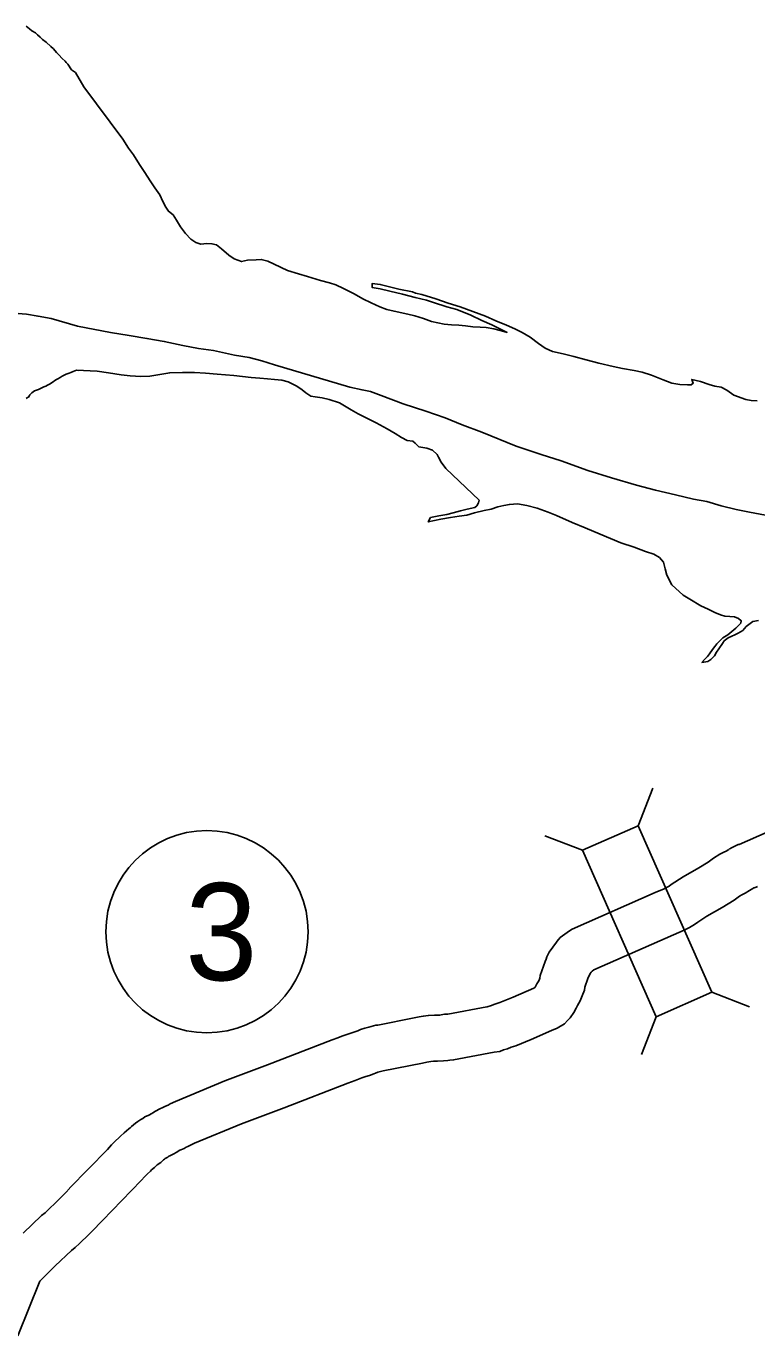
# Model space of a CAD drawing. Extents: x -939622 to -934245, y 1383184 to 1385301.
# Drawn here: x -936310.87 to -936296.56, y 1384600.92 to 1384626.57 of the extents above; entities that cross this region are included whole.
import ezdxf

# ---------------------------------------------------------------- set-up
doc = ezdxf.new("R2010")
doc.units = 0
for name, color, linetype in [('Level 10', 7, 'Continuous'), ('Level 2', 7, 'Continuous'), ('Level 20', 7, 'Continuous'), ('Level 27', 7, 'Continuous'), ('Level 9', 7, 'Continuous')]:
    doc.layers.add(name, color=color, linetype=linetype)

msp = doc.modelspace()

# ---------------------------------------------------------------- linework, layer by layer
at = {"layer": 'Level 10'}
for points in [[(-936297.105, 1384610.446), (-936297.057, 1384610.474), (-936296.99, 1384610.509), (-936296.924, 1384610.536), (-936296.91, 1384610.542), (-936295.814, 1384611.024)], [(-936310.016, 1384603.805), (-936309.275, 1384604.567), (-936309.198, 1384604.656), (-936309.119, 1384604.733), (-936309.055, 1384604.795), (-936309.022, 1384604.826), (-936308.95, 1384604.893), (-936308.86, 1384604.967), (-936308.832, 1384604.988), (-936308.804, 1384605.017), (-936308.725, 1384605.078), (-936308.681, 1384605.111), (-936308.62, 1384605.153), (-936308.583, 1384605.173), (-936308.541, 1384605.205), (-936308.466, 1384605.241), (-936308.409, 1384605.272), (-936308.386, 1384605.284), (-936308.338, 1384605.317), (-936308.251, 1384605.362), (-936308.192, 1384605.388), (-936308.167, 1384605.399), (-936308.139, 1384605.414), (-936308.09, 1384605.436), (-936308.049, 1384605.457), (-936307.943, 1384605.508), (-936306.979, 1384605.908), (-936306.14, 1384606.221), (-936304.879, 1384606.712), (-936304.766, 1384606.75), (-936304.688, 1384606.787), (-936304.572, 1384606.822), (-936304.509, 1384606.844), (-936304.453, 1384606.863), (-936304.377, 1384606.892), (-936304.323, 1384606.913), (-936304.237, 1384606.94), (-936304.16, 1384606.961), (-936304.114, 1384606.976), (-936304.023, 1384606.999), (-936303.985, 1384607.003), (-936303.27, 1384607.144), (-936303.171, 1384607.161), (-936303.093, 1384607.174), (-936302.993, 1384607.191), (-936302.87, 1384607.198), (-936302.815, 1384607.195), (-936302.771, 1384607.197), (-936302.743, 1384607.201), (-936302.675, 1384607.213), (-936302.609, 1384607.216), (-936301.85, 1384607.359), (-936301.842, 1384607.361), (-936301.756, 1384607.383), (-936301.712, 1384607.405), (-936301.594, 1384607.443), (-936301.33, 1384607.552), (-936300.93, 1384607.725), (-936300.906, 1384607.735), (-936300.902, 1384607.743), (-936300.868, 1384607.808), (-936300.833, 1384607.871), (-936300.82, 1384607.903), (-936300.812, 1384607.924), (-936300.804, 1384607.97), (-936300.708, 1384608.245), (-936300.687, 1384608.293), (-936300.672, 1384608.339), (-936300.627, 1384608.431), (-936300.487, 1384608.629), (-936300.472, 1384608.647), (-936300.414, 1384608.716), (-936300.412, 1384608.718), (-936300.231, 1384608.848), (-936300.178, 1384608.879), (-936298.55, 1384609.599), (-936298.375, 1384609.671), (-936298.32, 1384609.701), (-936298.28, 1384609.724), (-936298.24, 1384609.755), (-936298.007, 1384609.904), (-936297.698, 1384610.08), (-936297.515, 1384610.193), (-936297.409, 1384610.273), (-936297.283, 1384610.35), (-936297.205, 1384610.386), (-936297.161, 1384610.411), (-936297.11, 1384610.443)], [(-936296.642, 1384609.674), (-936296.619, 1384609.688), (-936296.615, 1384609.69), (-936296.573, 1384609.706), (-936296.546, 1384609.719)], [(-936309.37, 1384603.178), (-936308.613, 1384603.957), (-936308.543, 1384604.038), (-936308.491, 1384604.089), (-936308.436, 1384604.142), (-936308.411, 1384604.165), (-936308.358, 1384604.214), (-936308.3, 1384604.262), (-936308.232, 1384604.314), (-936308.201, 1384604.345), (-936308.179, 1384604.363), (-936308.158, 1384604.379), (-936308.148, 1384604.386), (-936308.095, 1384604.415), (-936308.072, 1384604.432), (-936308.057, 1384604.439), (-936307.99, 1384604.475), (-936307.918, 1384604.512), (-936307.87, 1384604.546), (-936307.862, 1384604.55), (-936307.838, 1384604.561), (-936307.773, 1384604.588), (-936307.736, 1384604.609), (-936307.701, 1384604.624), (-936307.648, 1384604.652), (-936307.575, 1384604.687), (-936306.649, 1384605.07), (-936305.819, 1384605.381), (-936304.571, 1384605.866), (-936304.428, 1384605.914), (-936304.363, 1384605.945), (-936304.294, 1384605.966), (-936304.214, 1384605.994), (-936304.144, 1384606.018), (-936304.059, 1384606.05), (-936304.03, 1384606.061), (-936303.979, 1384606.077), (-936303.901, 1384606.1), (-936303.875, 1384606.108), (-936303.106, 1384606.259), (-936303.021, 1384606.274), (-936302.943, 1384606.287), (-936302.894, 1384606.295), (-936302.867, 1384606.297), (-936302.814, 1384606.294), (-936302.697, 1384606.3), (-936302.612, 1384606.31), (-936302.571, 1384606.317), (-936302.5, 1384606.321), (-936301.706, 1384606.471), (-936301.593, 1384606.486), (-936301.52, 1384606.515), (-936301.442, 1384606.535), (-936301.373, 1384606.569), (-936301.282, 1384606.599), (-936300.98, 1384606.723), (-936300.582, 1384606.895), (-936300.468, 1384606.942), (-936300.33, 1384607.027), (-936300.267, 1384607.091), (-936300.217, 1384607.143), (-936300.143, 1384607.25), (-936300.1, 1384607.333), (-936300.075, 1384607.383), (-936300.022, 1384607.477), (-936299.983, 1384607.572), (-936299.938, 1384607.689), (-936299.929, 1384607.746), (-936299.869, 1384607.917), (-936299.828, 1384608.012), (-936299.807, 1384608.039), (-936299.801, 1384608.047), (-936299.786, 1384608.059), (-936299.754, 1384608.082), (-936298.196, 1384608.771), (-936297.983, 1384608.859), (-936297.883, 1384608.915), (-936297.78, 1384608.972), (-936297.719, 1384609.02), (-936297.542, 1384609.133), (-936297.239, 1384609.306), (-936297.005, 1384609.45), (-936296.903, 1384609.528), (-936296.857, 1384609.555), (-936296.792, 1384609.586), (-936296.705, 1384609.635), (-936296.638, 1384609.677)], [(-936310.02, 1384603.8), (-936310.091, 1384603.725), (-936310.157, 1384603.655), (-936310.24, 1384603.574), (-936310.319, 1384603.496), (-936310.392, 1384603.428), (-936310.448, 1384603.374), (-936310.495, 1384603.328), (-936310.565, 1384603.275), (-936310.929, 1384602.928)], [(-936309.366, 1384603.182), (-936309.437, 1384603.107), (-936309.514, 1384603.025), (-936309.609, 1384602.931), (-936309.696, 1384602.846), (-936309.773, 1384602.775), (-936309.823, 1384602.726), (-936309.907, 1384602.645), (-936309.98, 1384602.59), (-936310.3, 1384602.284), (-936310.599, 1384601.984), (-936311.028, 1384600.917)]]:
    msp.add_lwpolyline(points, dxfattribs=at)
at = {"layer": 'Level 2'}
for points in [[(-936309.862, 1384620.689), (-936310.381, 1384620.842), (-936310.635, 1384620.885), (-936310.86, 1384620.925), (-936311.108, 1384620.948)], [(-936309.862, 1384620.689), (-936310.381, 1384620.842), (-936310.635, 1384620.885), (-936310.86, 1384620.925), (-936311.108, 1384620.948)], [(-936309.862, 1384620.689), (-936309.218, 1384620.567), (-936308.849, 1384620.505), (-936308.504, 1384620.449), (-936308.165, 1384620.392), (-936307.802, 1384620.315), (-936307.494, 1384620.256), (-936307.203, 1384620.214), (-936306.789, 1384620.125), (-936306.504, 1384620.08), (-936306.252, 1384620.014), (-936306.003, 1384619.936), (-936304.532, 1384619.499), (-936304.292, 1384619.441), (-936304.127, 1384619.41), (-936303.917, 1384619.334), (-936303.484, 1384619.171), (-936303.043, 1384619.026), (-936302.664, 1384618.892), (-936302.334, 1384618.76), (-936301.943, 1384618.614), (-936301.276, 1384618.343), (-936300.787, 1384618.177), (-936300.39, 1384618.055), (-936299.868, 1384617.863), (-936299.408, 1384617.718), (-936298.916, 1384617.579), (-936298.544, 1384617.478), (-936298.154, 1384617.386), (-936297.8, 1384617.3), (-936297.539, 1384617.255), (-936297.257, 1384617.171), (-936296.963, 1384617.099), (-936296.705, 1384617.048), (-936296.393, 1384616.988)], [(-936309.862, 1384620.689), (-936309.218, 1384620.567), (-936308.849, 1384620.505), (-936308.504, 1384620.449), (-936308.165, 1384620.392), (-936307.802, 1384620.315), (-936307.494, 1384620.256), (-936307.203, 1384620.214), (-936306.789, 1384620.125), (-936306.504, 1384620.08), (-936306.252, 1384620.014), (-936306.003, 1384619.936), (-936304.532, 1384619.499), (-936304.292, 1384619.441), (-936304.127, 1384619.41), (-936303.917, 1384619.334), (-936303.484, 1384619.171), (-936303.043, 1384619.026), (-936302.664, 1384618.892), (-936302.334, 1384618.76), (-936301.943, 1384618.614), (-936301.276, 1384618.343), (-936300.787, 1384618.177), (-936300.39, 1384618.055), (-936299.868, 1384617.863), (-936299.408, 1384617.718), (-936298.916, 1384617.579), (-936298.544, 1384617.478), (-936298.154, 1384617.386), (-936297.8, 1384617.3), (-936297.539, 1384617.255), (-936297.257, 1384617.171), (-936296.963, 1384617.099), (-936296.705, 1384617.048), (-936296.393, 1384616.988)]]:
    msp.add_lwpolyline(points, dxfattribs=at)
at = {"layer": 'Level 20'}
for p, q in [((-936298.887, 1384610.906), (-936298.601, 1384611.645)), ((-936299.973, 1384610.426), (-936300.712, 1384610.711)), ((-936297.445, 1384607.647), (-936296.707, 1384607.361)), ((-936298.532, 1384607.166), (-936298.818, 1384606.428))]:
    msp.add_line(p, q, dxfattribs=at)
msp.add_lwpolyline([(-936299.973, 1384610.426), (-936298.532, 1384607.166), (-936297.445, 1384607.647), (-936298.887, 1384610.906)], close=True, dxfattribs=at)
at = {"layer": 'Level 27'}
msp.add_ellipse((-936307.328, 1384608.831), major_axis=(0, 1.98), ratio=0.999998, dxfattribs=at)
at = {"layer": 'Level 9'}
for points in [[(-936309.901, 1384625.657), (-936309.979, 1384625.713), (-936310.052, 1384625.821), (-936310.085, 1384625.857), (-936310.106, 1384625.878), (-936310.163, 1384625.934), (-936310.23, 1384626.003), (-936310.275, 1384626.053), (-936310.335, 1384626.125), (-936310.383, 1384626.167), (-936310.474, 1384626.253), (-936310.549, 1384626.307), (-936310.591, 1384626.348), (-936310.645, 1384626.393), (-936310.687, 1384626.438), (-936310.754, 1384626.476), (-936310.805, 1384626.515), (-936310.868, 1384626.565)], [(-936309.901, 1384625.657), (-936309.979, 1384625.713), (-936310.052, 1384625.821), (-936310.085, 1384625.857), (-936310.106, 1384625.878), (-936310.163, 1384625.934), (-936310.23, 1384626.003), (-936310.275, 1384626.053), (-936310.335, 1384626.125), (-936310.383, 1384626.167), (-936310.474, 1384626.253), (-936310.549, 1384626.307), (-936310.591, 1384626.348), (-936310.645, 1384626.393), (-936310.687, 1384626.438), (-936310.754, 1384626.476), (-936310.805, 1384626.515), (-936310.868, 1384626.565)], [(-936309.901, 1384625.657), (-936309.741, 1384625.378), (-936308.973, 1384624.354), (-936308.864, 1384624.175), (-936308.766, 1384624.047), (-936308.648, 1384623.856), (-936308.544, 1384623.698), (-936308.441, 1384623.54), (-936308.35, 1384623.4), (-936308.252, 1384623.26), (-936308.191, 1384623.129), (-936308.136, 1384623.019), (-936308.082, 1384622.941), (-936307.988, 1384622.87), (-936307.921, 1384622.769), (-936307.848, 1384622.638), (-936307.751, 1384622.507), (-936307.645, 1384622.397), (-936307.545, 1384622.326), (-936307.446, 1384622.297), (-936307.33, 1384622.307), (-936307.231, 1384622.305), (-936307.144, 1384622.282), (-936307.044, 1384622.205), (-936306.899, 1384622.078), (-936306.797, 1384622.007), (-936306.65, 1384621.954), (-936306.536, 1384621.983), (-936306.366, 1384621.991), (-936306.264, 1384621.998), (-936306.135, 1384621.963), (-936306.015, 1384621.907), (-936305.75, 1384621.781), (-936305.534, 1384621.714), (-936305.357, 1384621.662), (-936305.108, 1384621.587), (-936304.928, 1384621.538), (-936304.805, 1384621.5), (-936304.654, 1384621.43), (-936304.447, 1384621.321), (-936304.275, 1384621.224), (-936304.11, 1384621.145), (-936303.944, 1384621.069), (-936303.809, 1384621.019), (-936303.665, 1384620.982), (-936303.398, 1384620.927), (-936303.257, 1384620.893), (-936303.086, 1384620.841), (-936302.933, 1384620.785), (-936302.684, 1384620.731), (-936302.543, 1384620.718), (-936302.399, 1384620.71), (-936302.267, 1384620.694), (-936302.124, 1384620.68), (-936301.977, 1384620.67), (-936301.863, 1384620.665), (-936301.71, 1384620.64), (-936301.584, 1384620.605), (-936301.452, 1384620.567), (-936301.753, 1384620.714), (-936301.945, 1384620.802), (-936302.162, 1384620.905), (-936302.438, 1384621.016), (-936302.633, 1384621.068), (-936302.892, 1384621.152), (-936303.03, 1384621.199), (-936303.249, 1384621.253), (-936303.501, 1384621.319), (-936303.747, 1384621.374), (-936303.936, 1384621.42), (-936304.095, 1384621.448), (-936304.09, 1384621.529), (-936303.934, 1384621.507), (-936303.568, 1384621.412), (-936303.304, 1384621.361), (-936303.247, 1384621.34), (-936303.121, 1384621.312), (-936302.845, 1384621.228), (-936302.604, 1384621.143), (-936302.37, 1384621.068), (-936302.121, 1384620.98), (-936301.874, 1384620.887), (-936301.673, 1384620.793), (-936301.463, 1384620.708), (-936301.297, 1384620.641), (-936301.156, 1384620.568), (-936301.002, 1384620.473), (-936300.839, 1384620.349), (-936300.704, 1384620.258), (-936300.562, 1384620.193), (-936300.352, 1384620.147), (-936300.142, 1384620.099), (-936299.902, 1384620.032), (-936299.653, 1384619.969), (-936299.374, 1384619.903), (-936299.194, 1384619.863), (-936298.964, 1384619.823), (-936298.805, 1384619.789), (-936298.627, 1384619.728), (-936298.393, 1384619.637), (-936298.225, 1384619.576)], [(-936309.901, 1384625.657), (-936309.741, 1384625.378), (-936308.973, 1384624.354), (-936308.864, 1384624.175), (-936308.766, 1384624.047), (-936308.648, 1384623.856), (-936308.544, 1384623.698), (-936308.441, 1384623.54), (-936308.35, 1384623.4), (-936308.252, 1384623.26), (-936308.191, 1384623.129), (-936308.136, 1384623.019), (-936308.082, 1384622.941), (-936307.988, 1384622.87), (-936307.921, 1384622.769), (-936307.848, 1384622.638), (-936307.751, 1384622.507), (-936307.645, 1384622.397), (-936307.545, 1384622.326), (-936307.446, 1384622.297), (-936307.33, 1384622.307), (-936307.231, 1384622.305), (-936307.144, 1384622.282), (-936307.044, 1384622.205), (-936306.899, 1384622.078), (-936306.797, 1384622.007), (-936306.65, 1384621.954), (-936306.536, 1384621.983), (-936306.366, 1384621.991), (-936306.264, 1384621.998), (-936306.135, 1384621.963), (-936306.015, 1384621.907), (-936305.75, 1384621.781), (-936305.534, 1384621.714), (-936305.357, 1384621.662), (-936305.108, 1384621.587), (-936304.928, 1384621.538), (-936304.805, 1384621.5), (-936304.654, 1384621.43), (-936304.447, 1384621.321), (-936304.275, 1384621.224), (-936304.11, 1384621.145), (-936303.944, 1384621.069), (-936303.809, 1384621.019), (-936303.665, 1384620.982), (-936303.398, 1384620.927), (-936303.257, 1384620.893), (-936303.086, 1384620.841), (-936302.933, 1384620.785), (-936302.684, 1384620.731), (-936302.543, 1384620.718), (-936302.399, 1384620.71), (-936302.267, 1384620.694), (-936302.124, 1384620.68), (-936301.977, 1384620.67), (-936301.863, 1384620.665), (-936301.71, 1384620.64), (-936301.584, 1384620.605), (-936301.452, 1384620.567), (-936301.753, 1384620.714), (-936301.945, 1384620.802), (-936302.162, 1384620.905), (-936302.438, 1384621.016), (-936302.633, 1384621.068), (-936302.892, 1384621.152), (-936303.03, 1384621.199), (-936303.249, 1384621.253), (-936303.501, 1384621.319), (-936303.747, 1384621.374), (-936303.936, 1384621.42), (-936304.095, 1384621.448), (-936304.09, 1384621.529), (-936303.934, 1384621.507), (-936303.568, 1384621.412), (-936303.304, 1384621.361), (-936303.247, 1384621.34), (-936303.121, 1384621.312), (-936302.845, 1384621.228), (-936302.604, 1384621.143), (-936302.37, 1384621.068), (-936302.121, 1384620.98), (-936301.874, 1384620.887), (-936301.673, 1384620.793), (-936301.463, 1384620.708), (-936301.297, 1384620.641), (-936301.156, 1384620.568), (-936301.002, 1384620.473), (-936300.839, 1384620.349), (-936300.704, 1384620.258), (-936300.562, 1384620.193), (-936300.352, 1384620.147), (-936300.142, 1384620.099), (-936299.902, 1384620.032), (-936299.653, 1384619.969), (-936299.374, 1384619.903), (-936299.194, 1384619.863), (-936298.964, 1384619.823), (-936298.805, 1384619.789), (-936298.627, 1384619.728), (-936298.393, 1384619.637), (-936298.225, 1384619.576)], [(-936309.835, 1384619.822), (-936309.88, 1384619.828), (-936309.916, 1384619.813), (-936309.946, 1384619.801), (-936309.996, 1384619.785), (-936310.029, 1384619.77), (-936310.083, 1384619.749), (-936310.125, 1384619.73), (-936310.161, 1384619.709), (-936310.199, 1384619.685), (-936310.25, 1384619.658), (-936310.277, 1384619.645), (-936310.304, 1384619.627), (-936310.342, 1384619.597), (-936310.369, 1384619.579), (-936310.396, 1384619.561), (-936310.426, 1384619.545), (-936310.45, 1384619.533), (-936310.485, 1384619.515), (-936310.524, 1384619.5), (-936310.56, 1384619.484), (-936310.587, 1384619.469), (-936310.626, 1384619.451), (-936310.667, 1384619.436), (-936310.703, 1384619.421), (-936310.733, 1384619.405), (-936310.757, 1384619.384), (-936310.775, 1384619.366), (-936310.795, 1384619.345), (-936310.801, 1384619.33), (-936310.825, 1384619.303), (-936310.843, 1384619.291), (-936310.87, 1384619.275)], [(-936309.835, 1384619.822), (-936309.88, 1384619.828), (-936309.916, 1384619.813), (-936309.946, 1384619.801), (-936309.996, 1384619.785), (-936310.029, 1384619.77), (-936310.083, 1384619.749), (-936310.125, 1384619.73), (-936310.161, 1384619.709), (-936310.199, 1384619.685), (-936310.25, 1384619.658), (-936310.277, 1384619.645), (-936310.304, 1384619.627), (-936310.342, 1384619.597), (-936310.369, 1384619.579), (-936310.396, 1384619.561), (-936310.426, 1384619.545), (-936310.45, 1384619.533), (-936310.485, 1384619.515), (-936310.524, 1384619.5), (-936310.56, 1384619.484), (-936310.587, 1384619.469), (-936310.626, 1384619.451), (-936310.667, 1384619.436), (-936310.703, 1384619.421), (-936310.733, 1384619.405), (-936310.757, 1384619.384), (-936310.775, 1384619.366), (-936310.795, 1384619.345), (-936310.801, 1384619.33), (-936310.825, 1384619.303), (-936310.843, 1384619.291), (-936310.87, 1384619.275)], [(-936309.88, 1384619.828), (-936309.476, 1384619.808), (-936309.257, 1384619.777), (-936309.005, 1384619.738), (-936308.832, 1384619.716), (-936308.625, 1384619.703), (-936308.448, 1384619.711), (-936308.057, 1384619.778), (-936307.806, 1384619.784), (-936307.572, 1384619.781), (-936307.357, 1384619.771), (-936307.126, 1384619.749), (-936306.965, 1384619.739), (-936306.8, 1384619.723), (-936306.629, 1384619.707), (-936306.464, 1384619.688), (-936306.29, 1384619.672), (-936306.141, 1384619.658), (-936306.003, 1384619.645), (-936305.859, 1384619.634), (-936305.736, 1384619.597), (-936305.571, 1384619.517), (-936305.465, 1384619.446), (-936305.393, 1384619.384), (-936305.296, 1384619.319), (-936305.209, 1384619.305), (-936305.075, 1384619.289), (-936304.936, 1384619.251), (-936304.732, 1384619.19), (-936304.506, 1384619.052), (-936304.368, 1384618.972), (-936304.187, 1384618.881), (-936304.013, 1384618.796), (-936303.802, 1384618.681), (-936303.643, 1384618.587), (-936303.516, 1384618.51), (-936303.405, 1384618.454), (-936303.297, 1384618.441), (-936303.252, 1384618.402), (-936303.182, 1384618.328), (-936303.026, 1384618.303), (-936302.915, 1384618.259), (-936302.821, 1384618.176), (-936302.794, 1384618.122), (-936302.745, 1384618.03), (-936302.654, 1384617.901), (-936301.998, 1384617.281), (-936302.009, 1384617.23), (-936302.045, 1384617.173), (-936302.086, 1384617.136), (-936302.233, 1384617.105), (-936302.364, 1384617.073), (-936302.504, 1384617.036), (-936302.633, 1384617.001), (-936302.785, 1384616.979), (-936302.949, 1384616.941), (-936302.996, 1384616.856), (-936302.748, 1384616.91), (-936302.557, 1384616.942), (-936302.39, 1384616.968), (-936302.237, 1384616.991), (-936302.088, 1384617.034), (-936301.903, 1384617.078), (-936301.76, 1384617.107), (-936301.635, 1384617.15), (-936301.515, 1384617.179), (-936301.405, 1384617.198), (-936301.249, 1384617.211), (-936301.063, 1384617.178), (-936300.865, 1384617.123), (-936300.649, 1384617.047), (-936300.481, 1384616.983), (-936300.18, 1384616.848), (-936299.925, 1384616.74), (-936299.63, 1384616.62), (-936299.224, 1384616.447), (-936298.966, 1384616.36), (-936298.741, 1384616.275), (-936298.576, 1384616.226), (-936298.47, 1384616.161), (-936298.391, 1384616.069), (-936298.354, 1384615.935), (-936298.326, 1384615.815), (-936298.228, 1384615.627), (-936298.005, 1384615.425), (-936297.872, 1384615.343), (-936297.655, 1384615.216), (-936297.514, 1384615.145), (-936297.387, 1384615.084), (-936297.276, 1384615.037), (-936297.186, 1384615.014), (-936297.087, 1384615.006), (-936297, 1384614.995), (-936296.919, 1384614.966), (-936296.865, 1384614.921), (-936296.877, 1384614.873), (-936296.974, 1384614.779), (-936297.048, 1384614.712), (-936297.129, 1384614.648), (-936297.227, 1384614.584), (-936297.286, 1384614.53)], [(-936309.88, 1384619.828), (-936309.476, 1384619.808), (-936309.257, 1384619.777), (-936309.005, 1384619.738), (-936308.832, 1384619.716), (-936308.625, 1384619.703), (-936308.448, 1384619.711), (-936308.057, 1384619.778), (-936307.806, 1384619.784), (-936307.572, 1384619.781), (-936307.357, 1384619.771), (-936307.126, 1384619.749), (-936306.965, 1384619.739), (-936306.8, 1384619.723), (-936306.629, 1384619.707), (-936306.464, 1384619.688), (-936306.29, 1384619.672), (-936306.141, 1384619.658), (-936306.003, 1384619.645), (-936305.859, 1384619.634), (-936305.736, 1384619.597), (-936305.571, 1384619.517), (-936305.465, 1384619.446), (-936305.393, 1384619.384), (-936305.296, 1384619.319), (-936305.209, 1384619.305), (-936305.075, 1384619.289), (-936304.936, 1384619.251), (-936304.732, 1384619.19), (-936304.506, 1384619.052), (-936304.368, 1384618.972), (-936304.187, 1384618.881), (-936304.013, 1384618.796), (-936303.802, 1384618.681), (-936303.643, 1384618.587), (-936303.516, 1384618.51), (-936303.405, 1384618.454), (-936303.297, 1384618.441), (-936303.252, 1384618.402), (-936303.182, 1384618.328), (-936303.026, 1384618.303), (-936302.915, 1384618.259), (-936302.821, 1384618.176), (-936302.794, 1384618.122), (-936302.745, 1384618.03), (-936302.654, 1384617.901), (-936301.998, 1384617.281), (-936302.009, 1384617.23), (-936302.045, 1384617.173), (-936302.086, 1384617.136), (-936302.233, 1384617.105), (-936302.364, 1384617.073), (-936302.504, 1384617.036), (-936302.633, 1384617.001), (-936302.785, 1384616.979), (-936302.949, 1384616.941), (-936302.996, 1384616.856), (-936302.748, 1384616.91), (-936302.557, 1384616.942), (-936302.39, 1384616.968), (-936302.237, 1384616.991), (-936302.088, 1384617.034), (-936301.903, 1384617.078), (-936301.76, 1384617.107), (-936301.635, 1384617.15), (-936301.515, 1384617.179), (-936301.405, 1384617.198), (-936301.249, 1384617.211), (-936301.063, 1384617.178), (-936300.865, 1384617.123), (-936300.649, 1384617.047), (-936300.481, 1384616.983), (-936300.18, 1384616.848), (-936299.925, 1384616.74), (-936299.63, 1384616.62), (-936299.224, 1384616.447), (-936298.966, 1384616.36), (-936298.741, 1384616.275), (-936298.576, 1384616.226), (-936298.47, 1384616.161), (-936298.391, 1384616.069), (-936298.354, 1384615.935), (-936298.326, 1384615.815), (-936298.228, 1384615.627), (-936298.005, 1384615.425), (-936297.872, 1384615.343), (-936297.655, 1384615.216), (-936297.514, 1384615.145), (-936297.387, 1384615.084), (-936297.276, 1384615.037), (-936297.186, 1384615.014), (-936297.087, 1384615.006), (-936297, 1384614.995), (-936296.919, 1384614.966), (-936296.865, 1384614.921), (-936296.877, 1384614.873), (-936296.974, 1384614.779), (-936297.048, 1384614.712), (-936297.129, 1384614.648), (-936297.227, 1384614.584), (-936297.286, 1384614.53)], [(-936298.225, 1384619.576), (-936298.069, 1384619.551), (-936297.922, 1384619.541), (-936297.85, 1384619.541), (-936297.806, 1384619.572), (-936297.818, 1384619.608), (-936297.837, 1384619.646), (-936297.666, 1384619.606), (-936297.494, 1384619.545), (-936297.383, 1384619.516), (-936297.26, 1384619.497), (-936297.149, 1384619.438), (-936297.013, 1384619.34), (-936296.776, 1384619.253), (-936296.674, 1384619.236), (-936296.554, 1384619.228)], [(-936298.225, 1384619.576), (-936298.069, 1384619.551), (-936297.922, 1384619.541), (-936297.85, 1384619.541), (-936297.806, 1384619.572), (-936297.818, 1384619.608), (-936297.837, 1384619.646), (-936297.666, 1384619.606), (-936297.494, 1384619.545), (-936297.383, 1384619.516), (-936297.26, 1384619.497), (-936297.149, 1384619.438), (-936297.013, 1384619.34), (-936296.776, 1384619.253), (-936296.674, 1384619.236), (-936296.554, 1384619.228)], [(-936297.286, 1384614.53), (-936297.342, 1384614.466), (-936297.386, 1384614.418), (-936297.431, 1384614.357), (-936297.487, 1384614.272), (-936297.528, 1384614.218), (-936297.584, 1384614.16), (-936297.637, 1384614.106), (-936297.521, 1384614.122), (-936297.459, 1384614.162), (-936297.393, 1384614.234), (-936297.349, 1384614.307), (-936297.308, 1384614.373), (-936297.234, 1384614.476), (-936297.202, 1384614.525), (-936297.125, 1384614.585), (-936297.05, 1384614.616), (-936296.991, 1384614.644), (-936296.925, 1384614.675), (-936296.836, 1384614.733), (-936296.771, 1384614.808), (-936296.643, 1384614.906), (-936296.527, 1384614.925)], [(-936297.286, 1384614.53), (-936297.342, 1384614.466), (-936297.386, 1384614.418), (-936297.431, 1384614.357), (-936297.487, 1384614.272), (-936297.528, 1384614.218), (-936297.584, 1384614.16), (-936297.637, 1384614.106), (-936297.521, 1384614.122), (-936297.459, 1384614.162), (-936297.393, 1384614.234), (-936297.349, 1384614.307), (-936297.308, 1384614.373), (-936297.234, 1384614.476), (-936297.202, 1384614.525), (-936297.125, 1384614.585), (-936297.05, 1384614.616), (-936296.991, 1384614.644), (-936296.925, 1384614.675), (-936296.836, 1384614.733), (-936296.771, 1384614.808), (-936296.643, 1384614.906), (-936296.527, 1384614.925)]]:
    msp.add_lwpolyline(points, dxfattribs=at)

# ---------------------------------------------------------------- texts
at = {"layer": 'Level 27'}
msp.add_text('3', height=1.901, dxfattribs=at).set_placement((-936307.754, 1384607.881))

doc.saveas('drawing.dxf')
